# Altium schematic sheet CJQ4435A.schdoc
size 127 x 101 mm
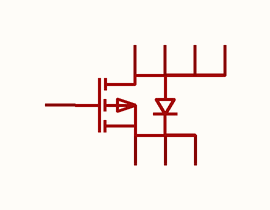
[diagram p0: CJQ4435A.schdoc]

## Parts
Q?  cjq4435a  [SOIC-8_L4.9-W3.9-P1.27-LS6.0-BL]  (value not drawn)

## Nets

Not connected (* = marked no-connect by the designer): Q? 1(S) 2(S) 3(S) 4(G) 5(D) 6(D) 7(D) 8(D)

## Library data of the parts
Q? = cjq4435a: 数量:1个P沟道;漏源电压(Vdss):30V;连续漏极电流(Id):9.9A;导通电阻(RDS(on)):25mΩ@4.5V;耗散功率(Pd):2.5W;阈值电压(Vgs(th)):2.2V;; Manufacturer: CJ(江苏长电/长晶); AddInBom: yes; ModelId: e81d2f7d937b4a6ab1dca543ff5d56a4; ModelName: SOIC-8_L4.9-W3.9-H1.7-LS6.0-P1.27; ModelTransform: 192.913,236.22,0,0,0,0,0,0,0; Number: 1个P沟道; Drain to Source Voltage: 30V; Current - Continuous Drain(Id): 9.9A; Pd - Power Dissipation: 2.5W; Gate Threshold Voltage (Vgs(th)): 2.2V; Gate Charge(Qg): 27nC@10V; Input Capacitance(Ciss): 1.395nF; Reverse Transfer Capacitance (Crss@Vds): 149pF; Type: P沟道; Output Capacitance(Coss): 202pF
